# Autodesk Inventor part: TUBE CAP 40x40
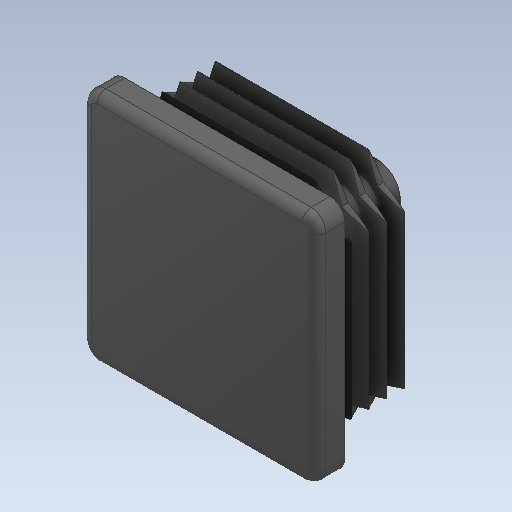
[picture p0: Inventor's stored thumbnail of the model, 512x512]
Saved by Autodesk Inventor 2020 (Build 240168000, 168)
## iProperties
Created: 1900-01
Part Number: TUBE CAP 40x40
Material: Générique
Document SubType Name: Modeling
Designer: bruno
Density: 1 g/cm^3
Appearance: Par défaut
Author: bruno
Revision Number: ANYUNSPECIFIED
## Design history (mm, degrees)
feature "Base1"
node "Solide1"
